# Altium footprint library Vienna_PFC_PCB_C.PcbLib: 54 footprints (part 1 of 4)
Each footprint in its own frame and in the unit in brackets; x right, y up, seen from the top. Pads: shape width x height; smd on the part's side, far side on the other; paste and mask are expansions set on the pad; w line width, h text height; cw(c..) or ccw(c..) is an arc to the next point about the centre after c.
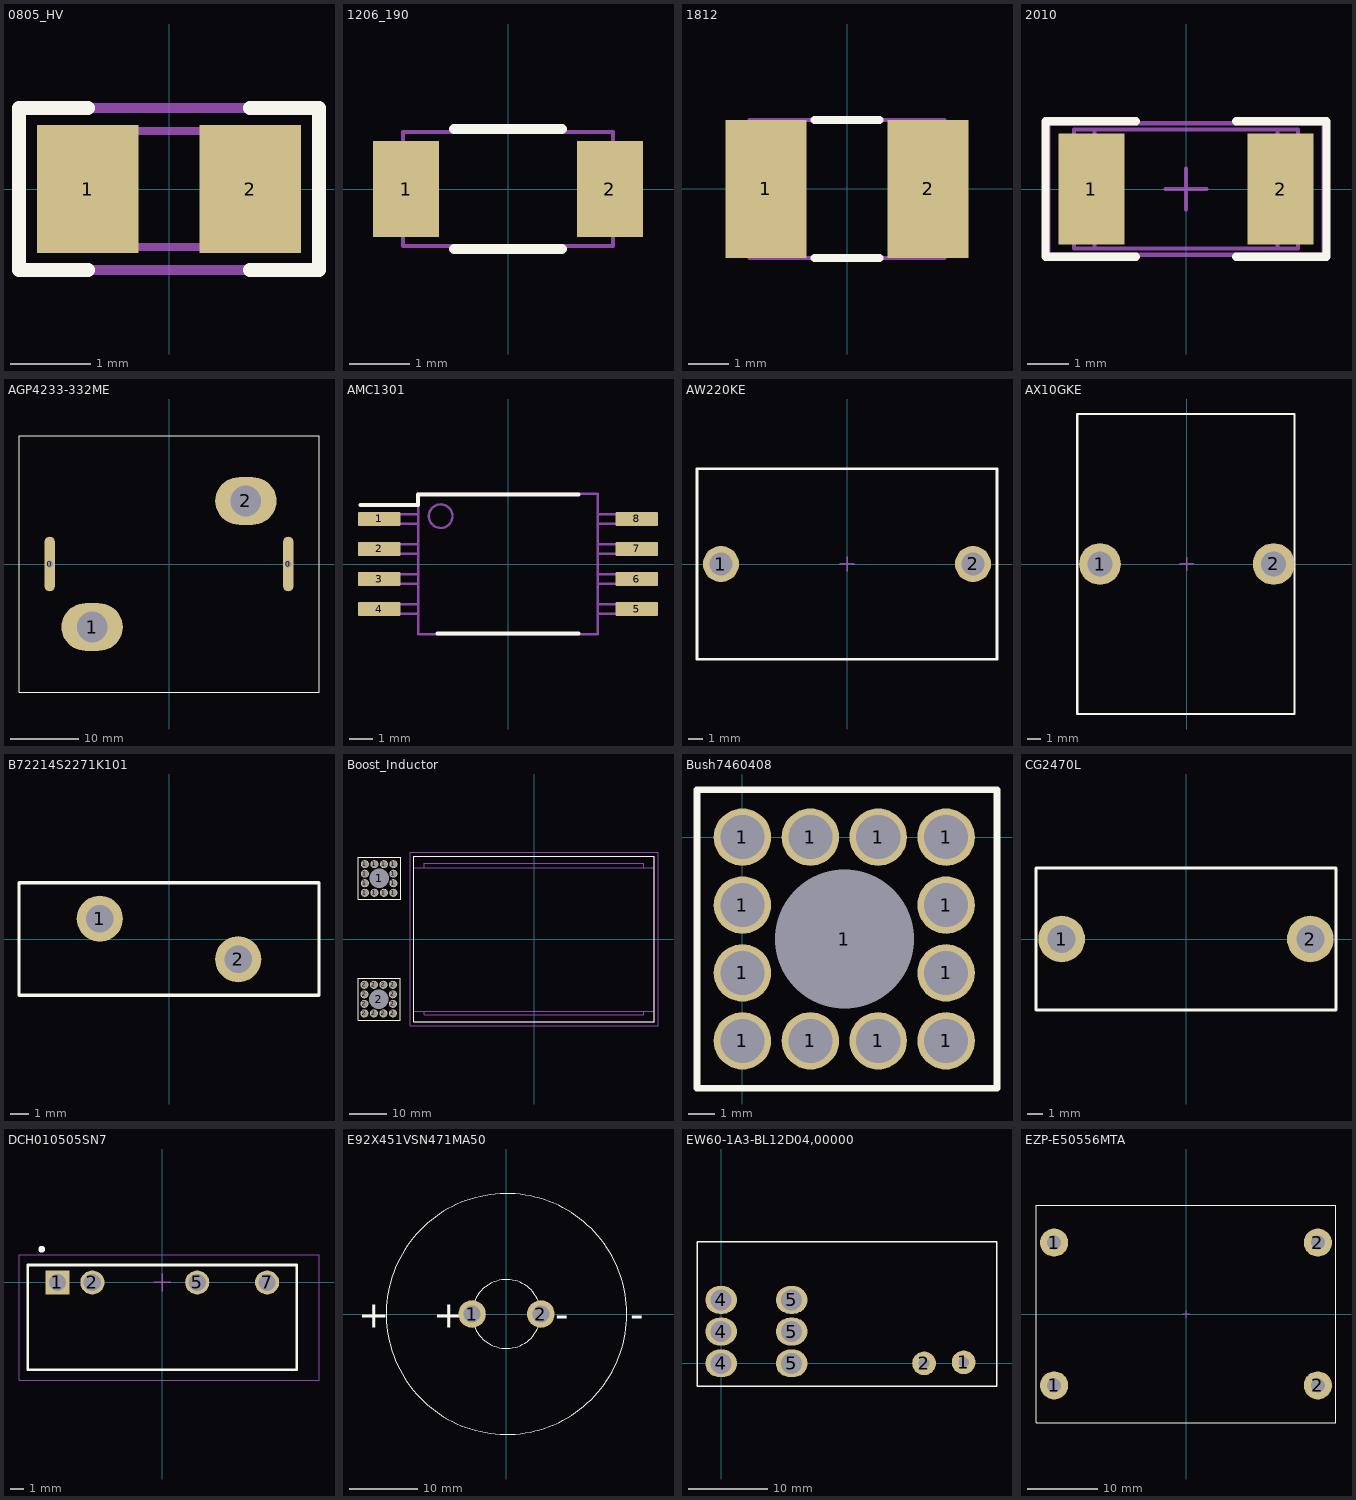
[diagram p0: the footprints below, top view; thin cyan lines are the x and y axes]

## 0805_HV [mil] "0805 with 30mil clearance between pads"
height 57.09
pads (2):
  rect 50x63 smd: 1(-40,0) 2(40,0)
Top Overlay:
  lines w7: -40,-40 -74,-40 -74,0 -74,40 -40,40 ; 40,-40 74,-40 74,0 74,40 40,40
Mechanical 5:
  lines w5: -74,-40 -74,40 74,40 74,-40 -74,-40
Mechanical 13:
  lines w3.94: -25.59,-28.54 -25.59,28.54 ; 25.59,-28.54 25.59,28.54 ; -43.31,-28.54 -43.31,28.54 43.31,28.54 43.31,-28.54 -43.31,-28.54
3D body: height 57.09, standoff 0, extent 25.61,-28.52 43.29,28.52
3D body: height 57.09, standoff 0, extent -25.57,-28.52 25.57,28.52
3D body: height 57.09, standoff 0, extent -43.29,-28.52 -25.61,28.52

## 1206_190 [mm] "1206_190"
height 1.9
pads (2):
  rect 1.1x1.6 smd: 1(-1.7,0) 2(1.7,0)
Top Overlay:
  lines w0.17: -0.9,-1 0.9,-1 ; -0.9,1 0.9,1
Mechanical 5:
  lines w0.07: -1.75,-0.95 -1.75,0.95 1.75,0.95 1.75,-0.95 -1.75,-0.95
3D body: height 1.9, standoff 0, extent 1.301,-0.949 1.749,0.949
3D body: height 1.9, standoff 0, extent -1.299,-0.949 1.299,0.949
3D body: height 1.9, standoff 0, extent -1.749,-0.949 -1.301,0.949

## 1812 [mm] "SMD, 2-Leads, Body 4.8x3.4mm"
height 2.54
pads (2):
  rect 2x3.4 smd: 1(-2,0) 2(2,0)
Top Overlay:
  lines w0.2: -0.8,-1.7 0.8,-1.7 ; -0.8,1.7 0.8,1.7
Mechanical 5:
  lines w0.1: -1.9,-1.7 -1.9,1.7 ; 1.9,-1.7 1.9,1.7 ; -2.4,-1.7 -2.4,1.7 2.4,1.7 2.4,-1.7 -2.4,-1.7
  text ".Designator" at -1.875,-0.5 h1.02
3D body: height 2.54, standoff 0, extent 1.901,-1.699 2.399,1.699
3D body: height 2.54, standoff 0, extent -1.899,-1.699 1.899,1.699
3D body: height 2.54, standoff 0, extent -2.399,-1.699 -1.901,1.699

## 2010 [mm] "Chip Capacitor, Body 5.08x2.54mm, IPC Medium Density"
height 1.66
pads (2):
  rect 1.6x2.7 smd: 1(-2.3,0) 2(2.3,0)
Top Overlay:
  lines w0.2: -1.219,-1.65 -3.419,-1.65 -3.419,1.65 -1.219,1.65 ; 1.219,-1.65 3.419,-1.65 3.419,1.65 1.219,1.65
Mechanical 5:
  lines w0.1: -2.73,-1.45 2.73,-1.45 2.73,1.45 -2.73,1.45 -2.73,-1.45
Mechanical 13:
  lines w0.1: -2.23,-1.45 -2.23,1.45 ; 2.23,-1.45 2.23,1.45 ; -2.73,-1.45 -2.73,1.45 2.73,1.45 2.73,-1.45 -2.73,-1.45
Mechanical 15:
  lines w0.1: -0.5,0 0.5,0 ; 0,-0.5 0,0.5 ; -3.35,-1.6 -3.35,1.6 3.35,1.6 3.35,-1.6 -3.35,-1.6
3D body: height 1.66, standoff 0, extent 2.231,-1.449 2.729,1.449
3D body: height 1.66, standoff 0, extent -2.229,-1.449 2.229,1.449
3D body: height 1.66, standoff 0, extent -2.729,-1.449 -2.231,1.449

## AGP4233-332ME [mm] "Inductor"
height 28
pads (4):
  oval 1.5x8 hole 1 square: 0(-17.5,0) 0(17.5,0)
  oval 9x7 hole 4.5 square: 1(-11.274,-9.25) 2(11.274,9.25)
Top Overlay:
  lines w0.178: -22,-18.8 22,-18.8 22,18.8 -22,18.8 -22,-18.8
3D body "Coilcraft-AGP4233_3_3-5_6uH.STEP": height 31.3, standoff -2, extent -21.6,-18.4 21.6,18.4

## AMC1301 [mm] "SOIC, 8-Leads, Body 5.95x7.6mm (max), Pitch 1.27mm"
height 2.8
pads (8):
  rrect17% 1.8x0.6 smd: 1(-5.45,1.905) 2(-5.45,0.635) 3(-5.45,-0.635) 4(-5.45,-1.905) 5(5.45,-1.905) 6(5.45,-0.635) 7(5.45,0.635) 8(5.45,1.905)
Top Overlay:
  lines w0.17: -6.25,2.5 -3.8,2.5 -3.8,2.95 2.975,2.95 ; -2.975,-2.95 2.975,-2.95
Mechanical 5:
  circle w0.1: c-2.85,2.025 r0.5
  lines w0.1: -3.805,-2.105 -5.8,-2.105 -5.8,-1.705 -3.805,-1.705 ; -3.805,-0.835 -5.8,-0.835 -5.8,-0.435 -3.805,-0.435 ; -3.805,0.435 -5.8,0.435 -5.8,0.835 -3.805,0.835 ; -3.805,1.705 -5.8,1.705 -5.8,2.105 -3.805,2.105 ; 3.805,-2.105 5.8,-2.105 5.8,-1.705 3.805,-1.705 ; 3.805,-0.835 5.8,-0.835 5.8,-0.435 3.805,-0.435 ; 3.805,0.435 5.8,0.435 5.8,0.835 3.805,0.835 ; 3.805,1.705 5.8,1.705 5.8,2.105 3.805,2.105 ; -3.8,-2.975 -3.8,2.975 3.8,2.975 3.8,-2.975 -3.8,-2.975
3D body "DWV0008A.stp": height 2.67, standoff -0.03, extent -5.768,-2.925 5.768,2.925

## AW220KE [mm] "Res"
pads (2):
  round 2.5 hole 1.6: 1(-8.75,0) 2(8.75,0)
Top Overlay:
  lines w0.178: -10.414,-6.604 10.414,-6.604 10.414,6.604 -10.414,6.604 -10.414,-6.604
Mechanical 15:
  lines w0.1: -0.5,0 0.5,0 ; 0,-0.5 0,0.5
3D body "AW220KE.stp": height 5.21, standoff -18.49, extent -10.033,-6.49 9.957,6.49

## AX10GKE [mm] "Res"
pads (2):
  round 3 hole 1.8: 1(-6.25,0) 2(6.25,0)
Top Overlay:
  lines w0.178: -7.874,-10.795 7.747,-10.795 7.747,10.795 -7.874,10.795 -7.874,-10.795
Mechanical 15:
  lines w0.1: -0.5,0 0.5,0 ; 0,-0.5 0,0.5
3D body "AX10GKE.stp": height 6.2, standoff -24.5, extent -7.535,-10.499 7.459,10.499

## B72214S2271K101 [mm] "Capacitor"
height 18.5
pads (2):
  round 2.5 hole 1.5: 1(-3.75,1.1) 2(3.75,-1.1)
Top Overlay:
  lines w0.178: -8.128,-3.048 -8.128,3.048 8.128,3.048 8.128,-3.048 -8.128,-3.048
3D body "User Library-S14K25 MOV.STEP": height 18.5, standoff -3, extent -7.75,-2.1 7.75,2.1

## Boost_Inductor [mm] "Boost_Inductor"
pads (26):
  round 2.15 hole 1.65: 1(-45.085,12.319) 1(-45.085,14.859) 1(-45.085,17.399) 1(-45.085,19.939) 1(-42.545,12.319) 1(-42.545,19.939) 1(-40.005,12.319) 1(-40.005,19.939) 1(-37.465,12.319) 1(-37.465,14.859) 1(-37.465,17.399) 1(-37.465,19.939) 2(-45.212,-19.812) 2(-45.212,-17.272) 2(-45.212,-14.732) 2(-45.212,-12.192) 2(-42.672,-19.812) 2(-42.672,-12.192) 2(-40.132,-19.812) 2(-40.132,-12.192) 2(-37.592,-19.812) 2(-37.592,-17.272) 2(-37.592,-14.732) 2(-37.592,-12.192)
  round 3.9 hole 5.2: 1(-41.275,16.129) 2(-41.402,-16.002)
Top Overlay:
  lines w0.1: -32.004,-22.098 -32.004,22.098 32.004,22.098 32.004,-22.098 -32.004,-22.098
  lines w0.254: -46.914,-21.59 -46.914,-10.414 -35.687,-10.414 -35.687,-21.59 -46.914,-21.59 ; -46.787,10.541 -35.56,10.541 -35.56,21.717 -46.787,21.717 -46.787,10.541
Mechanical 1:
  lines w0.1: 33.02,-5.969 33.02,23.114 21.59,23.114 -22.098,23.114 -33.02,23.114 -33.02,-23.114 -21.844,-23.114 21.844,-23.114 33.02,-23.114 33.02,-5.588
Mechanical 13:
  lines w0.013: -32.004,-19.191 31.996,-19.191 ; -32.004,19.009 31.996,19.009 ; -29.253,-19.191 -29.253,-20.191 29.244,-20.191 29.244,-19.191 ; -29.253,19.009 -29.253,20.209 29.244,20.209 29.244,19.009 ; -32.004,-22.091 31.996,-22.091 31.996,22.109 -32.004,22.109 -32.004,-22.091
3D body "Inductor_Mounting.STEP": height 71.62, standoff -7.38, extent -41,-22.102 41,22.098
3D body "Terminal.STEP": height 6, standoff -3.5, extent -45.8,-20.502 -36.8,-11.502
3D body "Terminal.STEP": height 6, standoff -3.5, extent -45.673,11.629 -36.673,20.629

## Bush7460408 [mm] "Power Connecter 12pin"
pads (13):
  round 2.15 hole 1.65: 1(0,-7.62) 1(0,-5.08) 1(0,-2.54) 1(0,0) 1(2.54,-7.62) 1(2.54,0) 1(5.08,-7.62) 1(5.08,0) 1(7.62,-7.62) 1(7.62,-5.08) 1(7.62,-2.54) 1(7.62,0)
  round 3.9 hole 5.2: 1(3.81,-3.81)
Top Overlay:
  lines w0.254: -1.702,-9.398 -1.702,1.778 9.525,1.778 9.525,-9.398 -1.702,-9.398
3D body "Terminal.STEP": height 6, standoff -3.5, extent -0.588,-8.31 8.412,0.69

## CG2470L [mm] "Capacitor"
height 8.5
pads (2):
  round 3 hole 1.8: 1(-8,0) 2(8,0)
Top Overlay:
  lines w0.178: -9.652,-4.572 -9.652,4.572 9.652,4.572 9.652,-4.572 -9.652,-4.572
3D body: height 8.5, standoff 0, extent -2.794,-4.064 3.04,4.064

## DCH010505SN7 [mm] "Module, 4-Leads, Body 19.56x7.62mm"
height 10.15
pads (4):
  rect 1.75x1.75 hole 1.25: 1(-7.62,0)
  round 1.75 hole 1.25: 2(-5.08,0) 5(2.54,0) 7(7.62,0)
Top Overlay:
  circle w0.25: c-8.761,2.413 r0.125
  lines w0.2: -9.78,-6.35 9.78,-6.35 9.78,1.27 -9.78,1.27 -9.78,-6.35
Mechanical 5:
  lines w0.1: -9.78,-6.35 9.78,-6.35 9.78,1.27 -9.78,1.27 -9.78,-6.35
Mechanical 15:
  lines w0.05: -10.41,-7.12 11.39,-7.12 11.39,2.02 -10.41,2.02 -10.41,-7.12
  lines w0.1: -0.635,0 0.635,0 ; 0,-0.635 0,0.635
3D body: height 10.15, standoff 0, extent -9.779,-6.35 9.779,1.27

## E92X451VSN471MA50 [mm] "Capacitor"
height 55
pads (2):
  round 4 hole 2.5: 1(-5,0) 2(5,0)
Top Overlay:
  circle w0.1: c0,0 r17.5
  circle w0.1: c0,0 r5
  text "-" at 7.112,-2.032 h4
  text "+" at -21.59,-2.032 h4
  text "+" at -10.668,-2.032 h4
  text "-" at 18.034,-2.032 h4
3D body "35x50_Snap.stp": height 50, standoff -4.02, extent -24.626,-24.624 24.113,24.115

## EW60-1A3-BL12D04,00000 [mm] "Capacitor"
pads (8):
  round 3 hole 1.35: 1(30.6,0.128) 2(25.6,0)
  oval 4x3.5 hole 2.65: 4(0,0) 4(0,4) 4(0,8) 5(8.9,0) 5(8.9,4) 5(8.9,8)
Top Overlay:
  lines w0.178: -3.048,-2.922 -3.048,15.366 34.798,15.366 34.798,-2.922 -3.048,-2.922
Mechanical 15:
  lines w0.1: -0.5,8 0.5,8 ; 0,7.5 0,8.5
3D body "EW60-1A3-BL12D04,00000.stp": height 30.4, standoff -4, extent -2.51,-2.378 34.29,14.822

## EZP-E50556MTA [mm] "Capacitor"
height 17
pads (4):
  round 4 hole 2: 1(-18.75,-10.15) 1(-18.75,10.15) 2(18.75,-10.15) 2(18.75,10.15)
Top Overlay:
  lines w0.178: -21.336,-15.494 21.336,-15.494 21.336,15.494 -21.336,15.494 -21.336,-15.494
Mechanical 15:
  lines w0.1: -0.5,0 0.5,0 ; 0,-0.5 0,0.5
3D body "FilmCap.STEP": height 51.5, standoff -4, extent -20.774,-15.007 20.726,14.993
